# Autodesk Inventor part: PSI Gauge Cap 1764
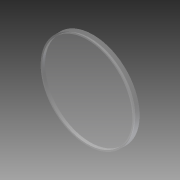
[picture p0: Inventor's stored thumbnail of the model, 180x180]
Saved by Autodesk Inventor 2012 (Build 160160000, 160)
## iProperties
Created: 2010-02
Part Number: PSI Gauge Cap 1764
Document SubType Name: Modeling
Designer: jgehrig
Density: 1 g/cm^3
Material: Default
Author: jgehrig
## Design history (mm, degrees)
sketch "Sketch1"
  geometry: C1 r 20.32 at (0, 0); C2 r 19.685 at (0, 0); 1 further point
  constraints: 2 centre point, 1 coincident
  dimensions: "d0" = 0 distance of C2.centre C1.centre; "d1" = 0 distance of point (0, 0) C2.centre; "d2" = 40.64 diameter of C1; "d3" = 39.37 diameter of C2
extrude "Extrusion1" new body sketch "Sketch1" distance "d4" = 1.27; taper "d5" = 0 deg
sketch "Sketch2"
  geometry: C1 r 20.32 at (0, 0) reference
extrude "Extrusion2" join sketch "Sketch2" distance "d6" = 1.27; taper "d7" = 0 deg
body "Solid1"
